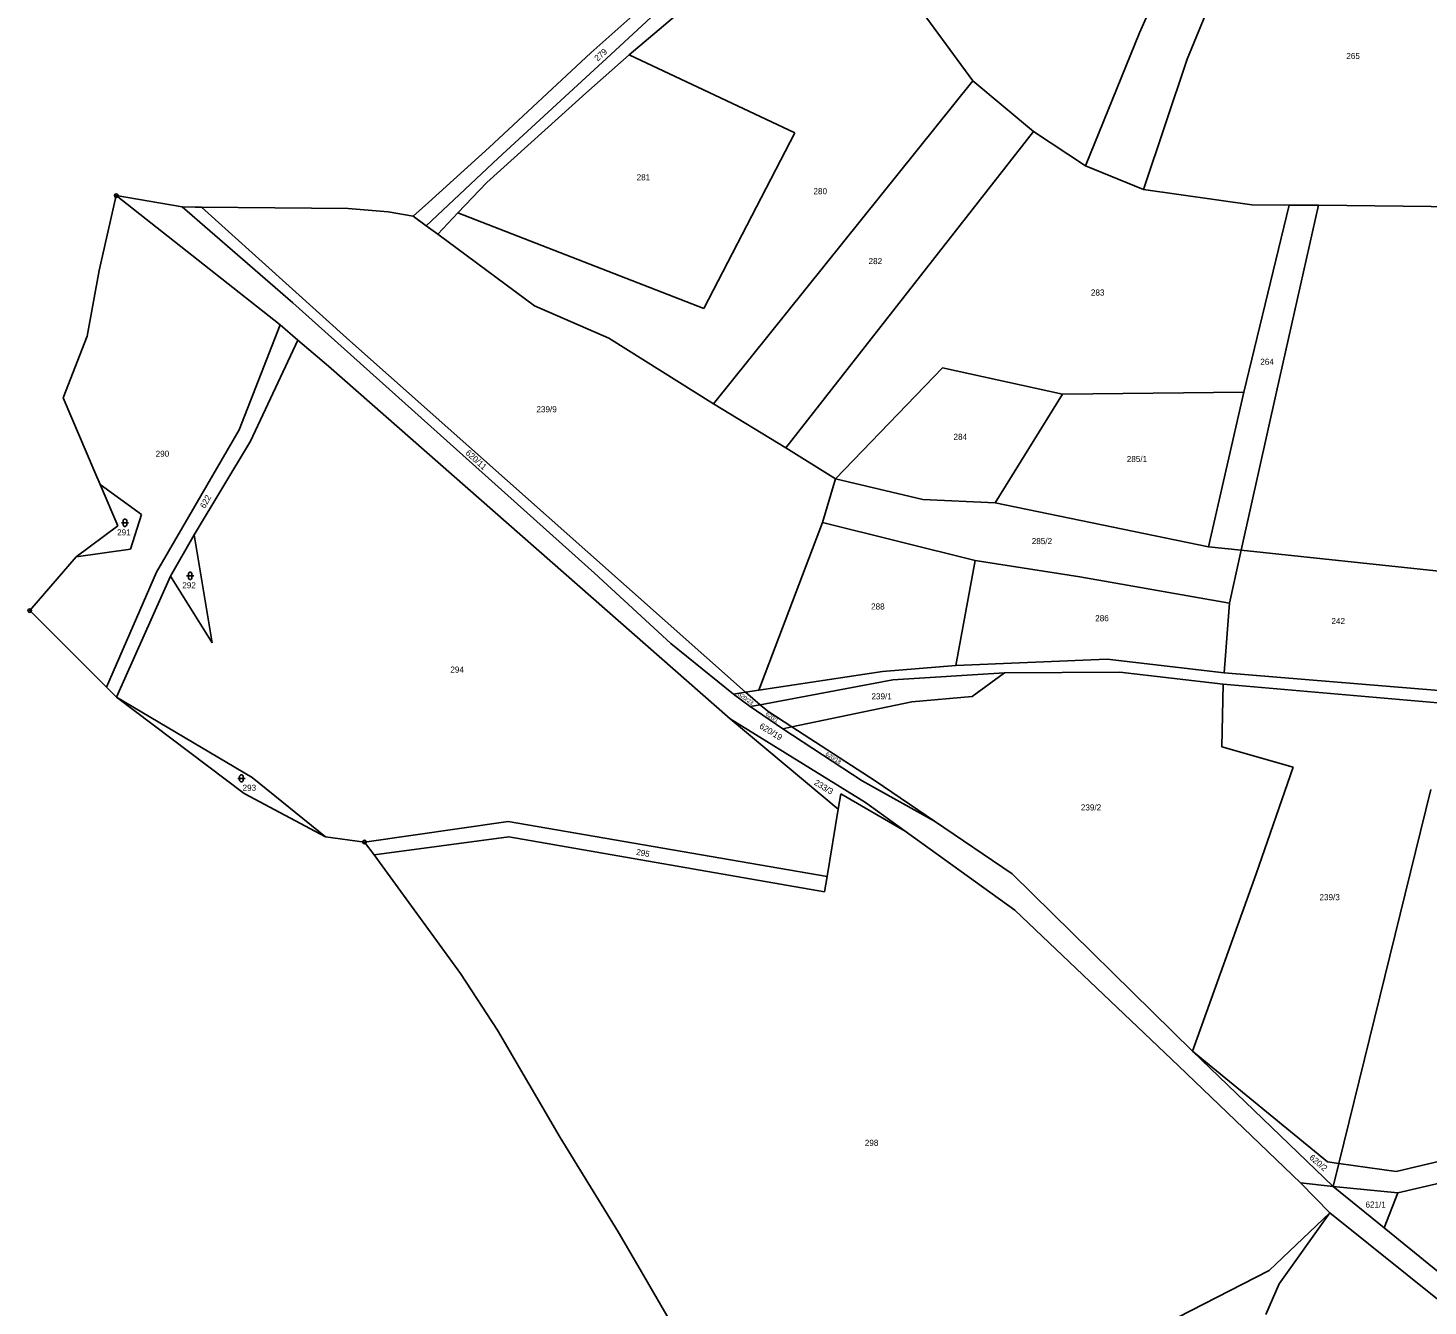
# Model space of a CAD drawing. Extents: x -794421 to -792735, y -1117671 to -1115559.
# Drawn here: x -794398.9 to -794007.8, y -1116238.3 to -1115881.2 of the extents above; entities that cross this region are included whole.
import ezdxf

# ---------------------------------------------------------------- set-up
doc = ezdxf.new("R2010")
doc.units = 0
for name, color, linetype in [('Vrstva 1', 7, 'Continuous'), ('Vrstva 14', 7, 'Continuous'), ('Vrstva 23', 7, 'Continuous'), ('Vrstva 28', 7, 'Continuous'), ('Vrstva 4', 7, 'Continuous')]:
    doc.layers.add(name, color=color, linetype=linetype)

msp = doc.modelspace()

# ---------------------------------------------------------------- linework, layer by layer
at = {"layer": 'Vrstva 1'}
for p, q in [((-794052.72, -1115802.53), (-794088.39, -1115882.59)), ((-794075.06, -1115889.96), (-794046.9, -1115821.13)), ((-794236.07, -1115888.59), (-794185.54, -1115841.76)), ((-794230.96, -1115888.7), (-794190.68, -1115854.56)), ((-794162.16, -1115858.87), (-794134.99, -1115895.95)), ((-794088.39, -1115882.59), (-794103.48, -1115919.75)), ((-794267.56, -1115917.56), (-794236.07, -1115888.59)), ((-794243.1, -1115899.41), (-794230.96, -1115888.7)), ((-794230.96, -1115888.7), (-794184.72, -1115910.48)), ((-794087.3, -1115926.37), (-794075.06, -1115889.96)), ((-794207.44, -1115986.21), (-794134.99, -1115895.95)), ((-794134.99, -1115895.95), (-794117.95, -1115910.13)), ((-794270.79, -1115924.38), (-794243.1, -1115899.41)), ((-794184.72, -1115910.48), (-794210.1, -1115959.57)), ((-794187.22, -1115998.57), (-794117.95, -1115910.13)), ((-794117.95, -1115910.13), (-794103.48, -1115919.75)), ((-794287.66, -1115936.48), (-794267.56, -1115917.56)), ((-794103.48, -1115919.75), (-794087.3, -1115926.37)), ((-794278.85, -1115932.88), (-794270.79, -1115924.38)), ((-794374.29, -1115928.06), (-794328.5, -1115964.19)), ((-794087.3, -1115926.37), (-794057.01, -1115930.61)), ((-794355.88, -1115931.22), (-794324.92, -1115958.02)), ((-794350.48, -1115931.27), (-794308.99, -1115968.67)), ((-794278.85, -1115932.88), (-794284.48, -1115938.82)), ((-794210.1, -1115959.57), (-794278.85, -1115932.88)), ((-794059.25, -1115982.95), (-794046.53, -1115930.69)), ((-794057.01, -1115930.61), (-794046.53, -1115930.69)), ((-794050.08, -1115982.93), (-794038.38, -1115930.69)), ((-794046.53, -1115930.69), (-794038.38, -1115930.69)), ((-794038.38, -1115930.69), (-793989.67, -1115931.27)), ((-794291.31, -1115933.79), (-794287.66, -1115936.48)), ((-794287.66, -1115936.48), (-794284.48, -1115938.82)), ((-794284.48, -1115938.82), (-794257.39, -1115958.88)), ((-794324.92, -1115958.02), (-794240.68, -1116033.59)), ((-794257.39, -1115958.88), (-794236.63, -1115967.88)), ((-794339.93, -1115993.53), (-794328.5, -1115964.19)), ((-794323.54, -1115968.43), (-794328.5, -1115964.19)), ((-794336.8, -1115996.66), (-794323.54, -1115968.43)), ((-794315.03, -1115975.71), (-794323.54, -1115968.43)), ((-794236.63, -1115967.88), (-794207.44, -1115986.21)), ((-794308.99, -1115968.67), (-794198.46, -1116066.85)), ((-794202.76, -1116074.25), (-794315.03, -1115975.71)), ((-794173.33, -1116007.22), (-794143.39, -1115976.14)), ((-794143.39, -1115976.14), (-794109.86, -1115983.52)), ((-794109.86, -1115983.52), (-794128.73, -1116013.94)), ((-794109.86, -1115983.52), (-794059.25, -1115982.95)), ((-794059.25, -1115982.95), (-794069.13, -1116026.19)), ((-794059.95, -1116027.16), (-794050.08, -1115982.93)), ((-794207.44, -1115986.21), (-794187.22, -1115998.57)), ((-794363.03, -1116033.26), (-794339.93, -1115993.53)), ((-794352.52, -1116022.82), (-794336.8, -1115996.66)), ((-794187.22, -1115998.57), (-794173.33, -1116007.22)), ((-794173.33, -1116007.22), (-794176.93, -1116019.4)), ((-794173.33, -1116007.22), (-794148.94, -1116012.97)), ((-794367.26, -1116017.12), (-794378.8, -1116008.79)), ((-794148.94, -1116012.97), (-794128.73, -1116013.94)), ((-794128.73, -1116013.94), (-794069.13, -1116026.19)), ((-794367.26, -1116017.12), (-794370.35, -1116026.85)), ((-794194.78, -1116066.28), (-794176.93, -1116019.4)), ((-794176.93, -1116019.4), (-794134.33, -1116030.01)), ((-794359.1, -1116034.39), (-794352.52, -1116022.82)), ((-794352.52, -1116022.82), (-794347.51, -1116053.06)), ((-794370.35, -1116026.85), (-794385.51, -1116029.02)), ((-794069.13, -1116026.19), (-794059.95, -1116027.16)), ((-794063.26, -1116041.97), (-794059.95, -1116027.16)), ((-794059.95, -1116027.16), (-794003.8, -1116033.12)), ((-794134.33, -1116030.01), (-794139.72, -1116059.36)), ((-794134.33, -1116030.01), (-794105.09, -1116034.62)), ((-794363.03, -1116033.26), (-794377.02, -1116065.41)), ((-794359.1, -1116034.39), (-794374.24, -1116068.19)), ((-794347.51, -1116053.06), (-794359.1, -1116034.39)), ((-794240.68, -1116033.59), (-794219.36, -1116053.2)), ((-794105.09, -1116034.62), (-794063.26, -1116041.97)), ((-794063.26, -1116041.97), (-794064.7, -1116061.44)), ((-794219.36, -1116053.2), (-794201.8, -1116067.36)), ((-794097.39, -1116057.63), (-794139.72, -1116059.36)), ((-794064.7, -1116061.44), (-794097.39, -1116057.63)), ((-794160.16, -1116061.05), (-794194.78, -1116066.28)), ((-794139.72, -1116059.36), (-794160.16, -1116061.05)), ((-794157.29, -1116063.36), (-794126.08, -1116061.4)), ((-794126.08, -1116061.4), (-794135.15, -1116068)), ((-794126.08, -1116061.4), (-794093.89, -1116061.22)), ((-794093.89, -1116061.22), (-794065.04, -1116064.56)), ((-794064.7, -1116061.44), (-794004.72, -1116066.36)), ((-794194.78, -1116066.28), (-794198.46, -1116066.85)), ((-794194.33, -1116070.33), (-794157.29, -1116063.36)), ((-794065.04, -1116064.56), (-794065.33, -1116082.09)), ((-794065.04, -1116064.56), (-794005.06, -1116069.79)), ((-794374.24, -1116068.19), (-794336.36, -1116090.68)), ((-794198.46, -1116066.85), (-794201.8, -1116067.36)), ((-794201.8, -1116067.36), (-794197.12, -1116070.86)), ((-794198.46, -1116066.85), (-794194.33, -1116070.33)), ((-794197.12, -1116070.86), (-794194.33, -1116070.33)), ((-794194.33, -1116070.33), (-794192.23, -1116072.11)), ((-794151.99, -1116069.53), (-794185.49, -1116076.5)), ((-794135.15, -1116068), (-794151.99, -1116069.53)), ((-794202.76, -1116074.25), (-794164.9, -1116097.63)), ((-794202.76, -1116074.25), (-794172.57, -1116099.47)), ((-794188.02, -1116077.03), (-794197.12, -1116070.86)), ((-794192.23, -1116072.11), (-794185.49, -1116076.5)), ((-794185.49, -1116076.5), (-794188.02, -1116077.03)), ((-794165.86, -1116091.63), (-794188.02, -1116077.03)), ((-794185.49, -1116076.5), (-794162.28, -1116091.62)), ((-794065.33, -1116082.09), (-794045.4, -1116087.81)), ((-794045.4, -1116087.81), (-794055.74, -1116117.61)), ((-794336.36, -1116090.68), (-794315.79, -1116107.19)), ((-794145.64, -1116102.88), (-794165.86, -1116091.63)), ((-794162.28, -1116091.62), (-794145.64, -1116102.88)), ((-794171.87, -1116095.24), (-794172.57, -1116099.47)), ((-794171.87, -1116095.24), (-794153.81, -1116105.64)), ((-794164.9, -1116097.63), (-794153.81, -1116105.64)), ((-794032.68, -1116198.52), (-794006.98, -1116093.99)), ((-794172.57, -1116099.47), (-794175.68, -1116118.31)), ((-794304.92, -1116108.69), (-794264.81, -1116102.99)), ((-794264.81, -1116102.99), (-794175.68, -1116118.31)), ((-794145.64, -1116102.88), (-794123.97, -1116117.54)), ((-794264.61, -1116107.22), (-794302.27, -1116112.26)), ((-794176.4, -1116122.65), (-794264.61, -1116107.22)), ((-794153.81, -1116105.64), (-794123.25, -1116127.7)), ((-794175.68, -1116118.31), (-794176.4, -1116122.65)), ((-794073.58, -1116167.12), (-794123.97, -1116117.54)), ((-794055.74, -1116117.61), (-794073.58, -1116167.12)), ((-794123.25, -1116127.7), (-794077.52, -1116171.22)), ((-794035.83, -1116198.07), (-794073.58, -1116167.12)), ((-794034.25, -1116204.92), (-794073.58, -1116167.12)), ((-794077.52, -1116171.22), (-794043.43, -1116203.95)), ((-794016.69, -1116200.78), (-793956.73, -1116186.47)), ((-794016.19, -1116206.71), (-793951.13, -1116191.65)), ((-794035.83, -1116198.07), (-794032.68, -1116198.52)), ((-794034.25, -1116204.92), (-794032.68, -1116198.52)), ((-794032.68, -1116198.52), (-794016.69, -1116200.78)), ((-794035.23, -1116212.34), (-794043.43, -1116203.95)), ((-794034.25, -1116204.92), (-794043.43, -1116203.95)), ((-794016.19, -1116206.71), (-794034.25, -1116204.92)), ((-794034.25, -1116204.92), (-794020.03, -1116216.53)), ((-794016.19, -1116206.71), (-794020.03, -1116216.53)), ((-794052.19, -1116228.41), (-794035.23, -1116212.34)), ((-794049.34, -1116232.18), (-794035.23, -1116212.34)), ((-794035.23, -1116212.34), (-794002.75, -1116238.27)), ((-794020.03, -1116216.53), (-793999.05, -1116233.58)), ((-794092.7, -1116249.17), (-794052.19, -1116228.41)), ((-794053.06, -1116240.71), (-794049.34, -1116232.18))]:
    msp.add_line(p, q, dxfattribs=at)
at = {"layer": 'Vrstva 23'}
for p, q in [((-794372.87, -1116019.48), (-794370.87, -1116019.48)), ((-794372.37, -1116018.88), (-794372.27, -1116018.68)), ((-794372.37, -1116020.08), (-794372.37, -1116018.88)), ((-794372.27, -1116018.68), (-794372.17, -1116018.58)), ((-794372.17, -1116018.58), (-794371.97, -1116018.48)), ((-794371.97, -1116018.48), (-794371.77, -1116018.48)), ((-794371.77, -1116018.48), (-794371.57, -1116018.58)), ((-794371.57, -1116018.58), (-794371.47, -1116018.68)), ((-794371.47, -1116018.68), (-794371.37, -1116018.88)), ((-794371.37, -1116018.88), (-794371.37, -1116020.08)), ((-794372.27, -1116020.28), (-794372.37, -1116020.08)), ((-794372.17, -1116020.38), (-794372.27, -1116020.28)), ((-794371.97, -1116020.48), (-794372.17, -1116020.38)), ((-794371.77, -1116020.48), (-794371.97, -1116020.48)), ((-794371.57, -1116020.38), (-794371.77, -1116020.48)), ((-794371.47, -1116020.28), (-794371.57, -1116020.38)), ((-794371.37, -1116020.08), (-794371.47, -1116020.28)), ((-794354.64, -1116034.31), (-794352.64, -1116034.31)), ((-794354.14, -1116033.71), (-794354.04, -1116033.51)), ((-794354.14, -1116034.91), (-794354.14, -1116033.71)), ((-794354.04, -1116035.11), (-794354.14, -1116034.91)), ((-794354.04, -1116033.51), (-794353.94, -1116033.41)), ((-794353.94, -1116035.21), (-794354.04, -1116035.11)), ((-794353.94, -1116033.41), (-794353.74, -1116033.31)), ((-794353.74, -1116033.31), (-794353.54, -1116033.31)), ((-794353.54, -1116033.31), (-794353.34, -1116033.41)), ((-794353.34, -1116033.41), (-794353.24, -1116033.51)), ((-794353.24, -1116035.11), (-794353.34, -1116035.21)), ((-794353.24, -1116033.51), (-794353.14, -1116033.71)), ((-794353.14, -1116034.91), (-794353.24, -1116035.11)), ((-794353.14, -1116033.71), (-794353.14, -1116034.91)), ((-794353.74, -1116035.31), (-794353.94, -1116035.21)), ((-794353.54, -1116035.31), (-794353.74, -1116035.31)), ((-794353.34, -1116035.21), (-794353.54, -1116035.31)), ((-794339.61, -1116090.01), (-794339.41, -1116089.91)), ((-794339.41, -1116089.91), (-794339.21, -1116089.91)), ((-794339.21, -1116089.91), (-794339.01, -1116090.01)), ((-794340.31, -1116090.91), (-794338.31, -1116090.91)), ((-794339.81, -1116090.31), (-794339.71, -1116090.11)), ((-794339.81, -1116091.51), (-794339.81, -1116090.31)), ((-794339.71, -1116091.71), (-794339.81, -1116091.51)), ((-794339.71, -1116090.11), (-794339.61, -1116090.01)), ((-794339.61, -1116091.81), (-794339.71, -1116091.71)), ((-794339.41, -1116091.91), (-794339.61, -1116091.81)), ((-794339.21, -1116091.91), (-794339.41, -1116091.91)), ((-794339.01, -1116091.81), (-794339.21, -1116091.91)), ((-794339.01, -1116090.01), (-794338.91, -1116090.11)), ((-794338.91, -1116091.71), (-794339.01, -1116091.81)), ((-794338.91, -1116090.11), (-794338.81, -1116090.31)), ((-794338.81, -1116091.51), (-794338.91, -1116091.71)), ((-794338.81, -1116090.31), (-794338.81, -1116091.51))]:
    msp.add_line(p, q, dxfattribs=at)
at = {"layer": 'Vrstva 28'}
for centre, radius in [((-794374.29, -1115928.06), 0.5), ((-794374.29, -1115928.06), 0.01), ((-794398.45, -1116044.01), 0.5), ((-794398.45, -1116044.01), 0.01), ((-794304.92, -1116108.69), 0.5), ((-794304.92, -1116108.69), 0.01)]:
    msp.add_circle(centre, radius, dxfattribs=at)
at = {"layer": 'Vrstva 4'}
for p, q in [((-794189.23, -1115841.46), (-794241.68, -1115888.13)), ((-794241.68, -1115888.13), (-794270.07, -1115914.63)), ((-794270.07, -1115914.63), (-794287.04, -1115929.94)), ((-794374.29, -1115928.06), (-794379.09, -1115948.98)), ((-794374.29, -1115928.06), (-794355.88, -1115931.22)), ((-794352.23, -1115931.25), (-794355.88, -1115931.22)), ((-794350.48, -1115931.27), (-794352.23, -1115931.25)), ((-794309.51, -1115931.67), (-794350.48, -1115931.27)), ((-794298.27, -1115932.58), (-794309.51, -1115931.67)), ((-794291.31, -1115933.79), (-794298.27, -1115932.58)), ((-794287.04, -1115929.94), (-794291.31, -1115933.79)), ((-794379.09, -1115948.98), (-794382.44, -1115967.3)), ((-794382.44, -1115967.3), (-794389.14, -1115984.56)), ((-794389.14, -1115984.56), (-794380.28, -1116005.33)), ((-794380.28, -1116005.33), (-794378.8, -1116008.79)), ((-794378.8, -1116008.79), (-794373.89, -1116020.29)), ((-794373.89, -1116020.29), (-794385.51, -1116029.02)), ((-794385.51, -1116029.02), (-794398.45, -1116044.01)), ((-794398.45, -1116044.01), (-794377.02, -1116065.41)), ((-794377.02, -1116065.41), (-794374.24, -1116068.19)), ((-794374.24, -1116068.19), (-794338.53, -1116095.15)), ((-794338.53, -1116095.15), (-794315.79, -1116107.19)), ((-794315.79, -1116107.19), (-794304.92, -1116108.69)), ((-794304.92, -1116108.69), (-794302.27, -1116112.26)), ((-794302.27, -1116112.26), (-794278.08, -1116145.38)), ((-794278.08, -1116145.38), (-794267.8, -1116161.25)), ((-794267.8, -1116161.25), (-794250.21, -1116191.23)), ((-794250.21, -1116191.23), (-794234.07, -1116217.6)), ((-794234.07, -1116217.6), (-794228.56, -1116227.05)), ((-794228.56, -1116227.05), (-794219.41, -1116242.72))]:
    msp.add_line(p, q, dxfattribs=at)

# ---------------------------------------------------------------- texts
at = {"layer": 'Vrstva 14'}
for s, height, rotation, p in [('279', 1.7, 41.98932, (-794239.755, -1115890.597)), ('620/11', 1.7, 317.91969, (-794276.865, -1116000.176)), ('622', 1.7, 61.27308, (-794349.515, -1116015.616)), ('620/23', 1.14, 324.31743, (-794200.669, -1116067.641)), ('620/1', 1.14, 326.01744, (-794192.998, -1116073.2)), ('620/19', 1.7, 328.58595, (-794194.784, -1116076.748)), ('620/18', 1.14, 328.18005, (-794176.254, -1116084.408)), ('233/3', 1.7, 328.4244, (-794179.46, -1116092.541)), ('295', 1.7, 349.29162, (-794229.134, -1116112.225)), ('620/2', 1.7, 319.24332, (-794041.085, -1116197.118))]:
    msp.add_text(s, height=height, rotation=rotation, dxfattribs=at).set_placement(p)
for s, p in [('265', (-794030.593, -1115889.89)), ('281', (-794228.89, -1115923.79)), ('280', (-794179.476, -1115927.66)), ('282', (-794164.086, -1115947.2)), ('283', (-794101.956, -1115955.98)), ('264', (-794054.632, -1115975.33)), ('239/9', (-794256.89, -1115988.6)), ('284', (-794140.342, -1115996.3)), ('290', (-794363.286, -1116001.04)), ('285/1', (-794091.929, -1116002.51)), ('291', (-794374.05, -1116023.01)), ('285/2', (-794118.486, -1116025.44)), ('292', (-794355.836, -1116037.79)), ('288', (-794163.376, -1116043.71)), ('286', (-794100.756, -1116046.99)), ('242', (-794034.742, -1116047.79)), ('294', (-794280.942, -1116061.35)), ('239/1', (-794163.273, -1116068.82)), ('293', (-794338.997, -1116094.37)), ('239/2', (-794104.77, -1116099.87)), ('239/3', (-794038.09, -1116124.94)), ('298', (-794165.126, -1116193.59)), ('621/1', (-794025.236, -1116210.84))]:
    msp.add_text(s, height=1.7, dxfattribs=at).set_placement(p)

doc.saveas('drawing.dxf')
